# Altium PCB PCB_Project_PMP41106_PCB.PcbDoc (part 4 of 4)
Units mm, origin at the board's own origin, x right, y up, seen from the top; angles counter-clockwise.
Board outline 190 x 100 mm, 2 copper layers (Top Layer, Bottom Layer), stack 1.646 mm thick; 219 components, 122 nets, 541 pads, 61 vias.
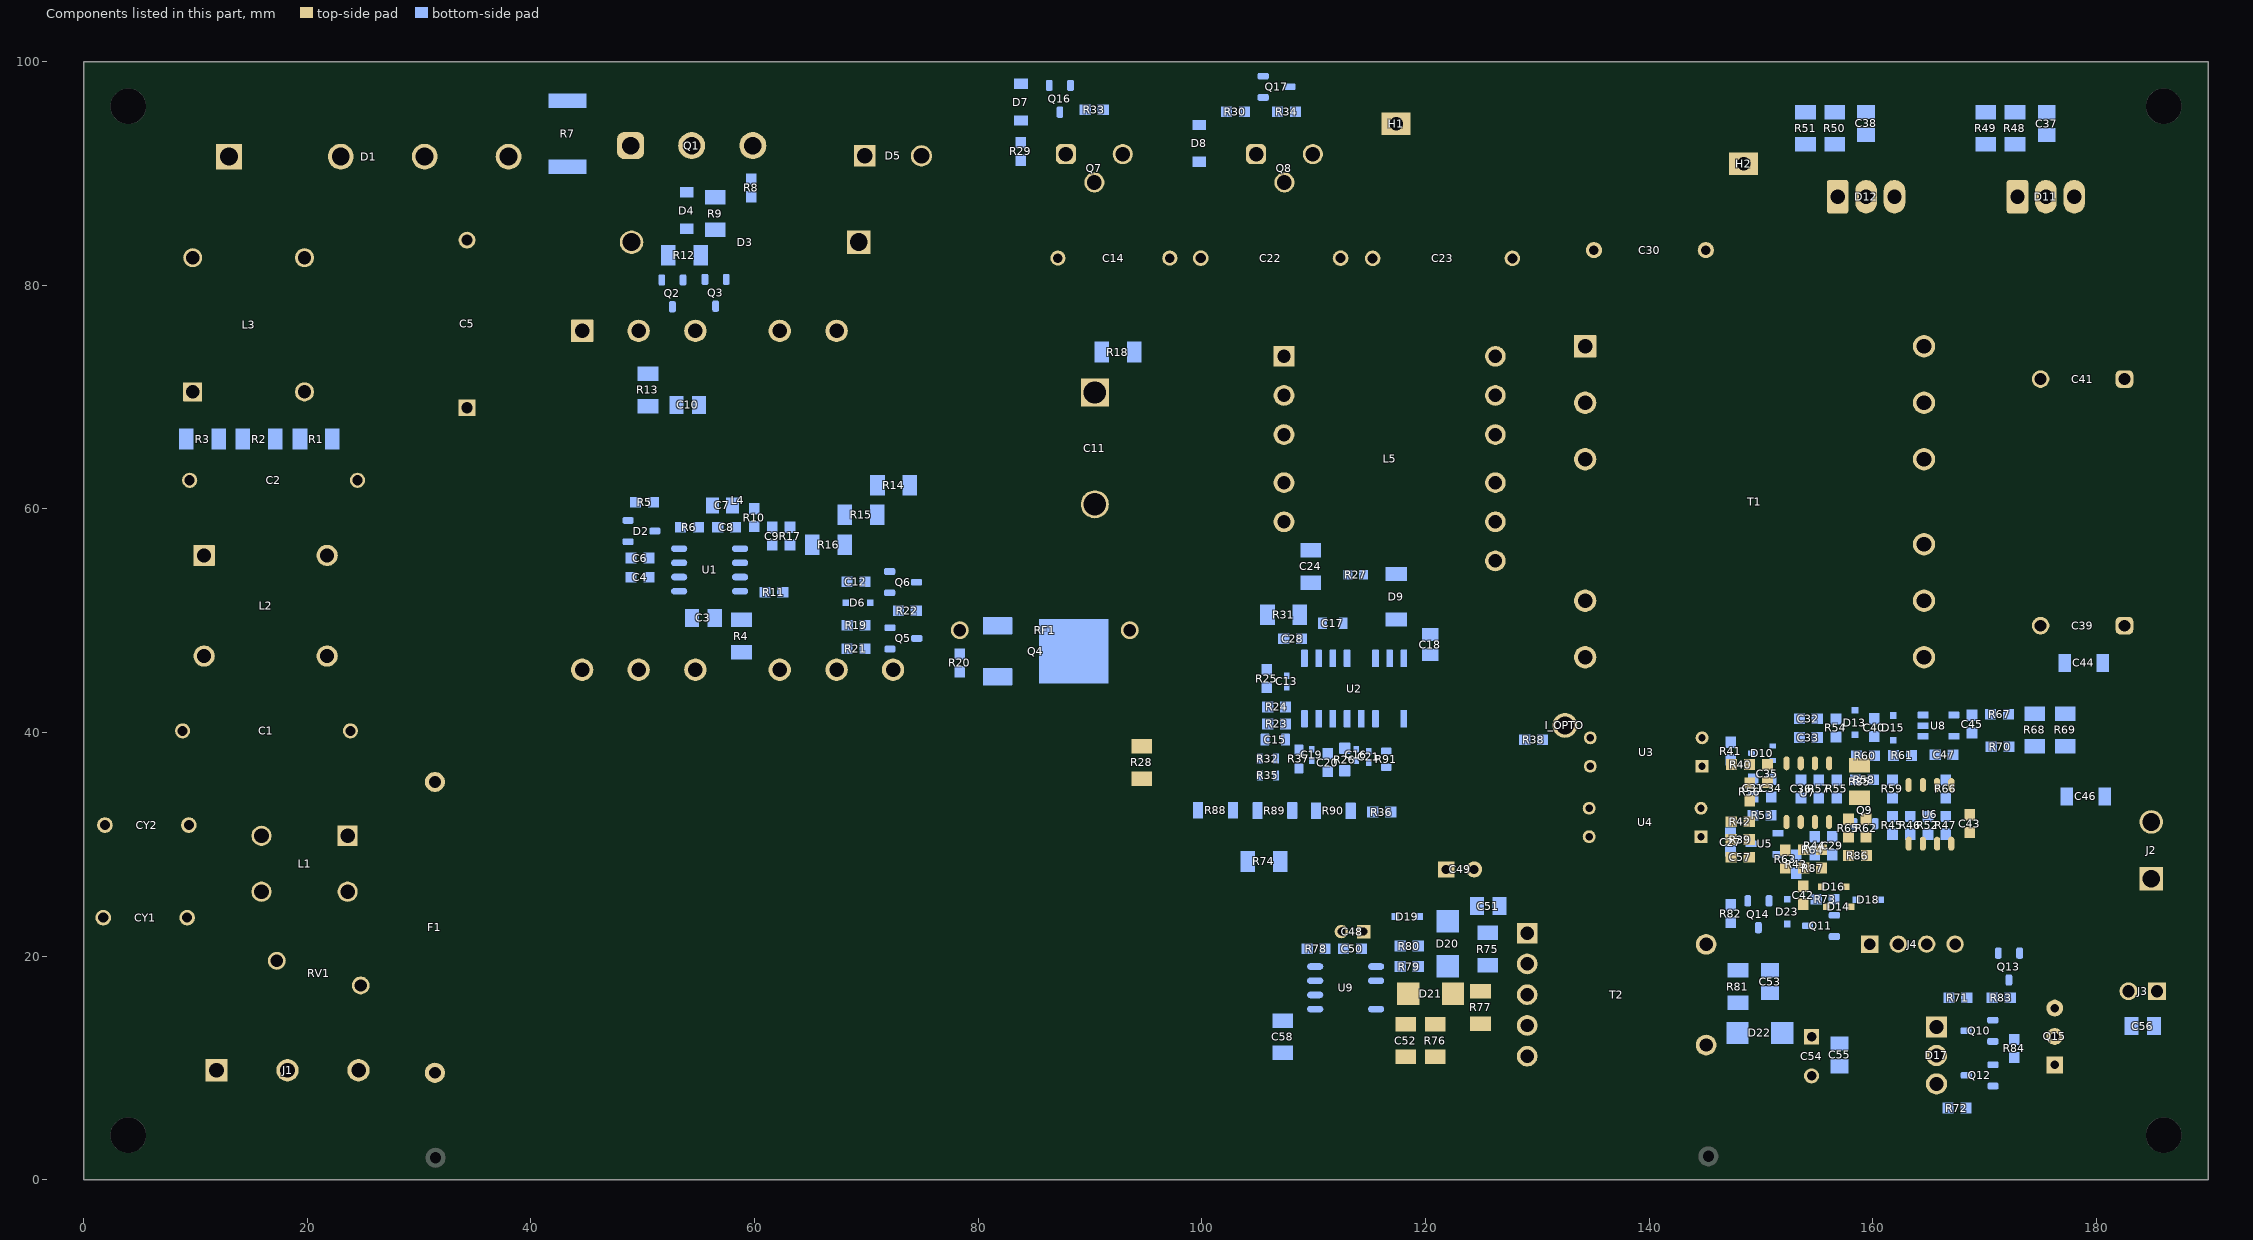
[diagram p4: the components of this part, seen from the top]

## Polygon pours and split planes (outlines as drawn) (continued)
NetD20_2 on Bottom Layer "Bottom Layer-No Net 38" (solid, pour order 150): 120.967,20.149 120.409,19.59 118.897,19.59 118.796,19.488 118.796,18.307 118.974,18.13 126.302,18.13 126.771,18.599 129.819,18.599 130.023,18.803 130.023,19.946 129.819,20.149
NetC51_1 on Bottom Layer "Bottom Layer-No Net 39" (solid, pour order 26): 124.638,22.79 125.197,22.79 125.959,23.552 125.959,25.28 126.06,25.381 127.229,25.381 127.279,25.33 127.279,23.527 126.467,22.714 126.467,21.444 126.441,21.419 124.739,21.419 124.638,21.52
PGND on Bottom Layer "Bottom Layer-No Net 40" (solid, pour order 152): 82.847,46.569 83.297,47.019 83.297,57.713 81.113,59.897 72.953,59.897 72.528,59.472 72.528,58.227 72.02,57.719 69.988,57.719 69.302,57.034 69.302,53.02 69.48,52.843 71.283,52.843 72.756,54.316 75.22,54.316 75.728,53.808 75.728,46.874 76.033,46.569
NetC49_1 on Bottom Layer "Bottom Layer-No Net 42" (solid, pour order 166): 122.631,26.067 123.266,25.432 125.146,25.432 125.247,25.33 125.247,23.603 125.044,23.4 123.215,23.4 123.012,23.197 123.012,22.13 122.911,22.028 120.98,22.028 120.853,22.155 120.853,22.867 120.523,23.197 119.126,23.197 119.024,23.298 119.024,24.137 119.863,24.975 119.863,28.727 122.631,28.727
PGND on Bottom Layer "Bottom Layer-No Net 43" (solid, pour order 170): 129.261,34.195 130.175,33.281 130.175,21.063 129.489,20.377 104.521,20.377 102.057,22.841 102.057,30.309 102.692,30.944 116.027,30.944 119.278,34.195
PGND on Bottom Layer "Bottom Layer-No Net 44" (solid, remove dead copper, pour order 174): 135.23,32.874 135.23,33.712 133.655,35.287 133.655,37.395 135.407,39.148 135.407,40.545 132.01,43.942 114.408,43.942 112.293,46.057 112.293,55.353 108.052,59.595 102.667,59.595 102.083,59.011 102.083,37.522 103.988,35.617 130.531,35.617 133.604,32.544 134.899,32.544
PGND on Bottom Layer "Bottom Layer-No Net 61" (solid, pour order 210): 57.36,73.209 54.432,70.282 54.432,61.754 64.142,61.754 64.313,61.925 64.313,72.625 63.729,73.209
NetC56_2 on Bottom Layer "Bottom Layer-No Net 45" (solid, remove dead copper, pour order 176): 176.308,17.787 175.209,16.688 175.209,15.011 175.844,14.376 175.87,14.402 180.543,14.402 182.118,12.859 183.693,12.859 183.82,12.986 183.82,17.406 183.439,17.787
NetQ13_3 on Bottom Layer "Bottom Layer-No Net 46" (solid, pour order 22): 171.958,18.364 172.517,18.364 173.279,17.602 173.279,14.275 173.939,13.614 176.784,13.614 177.19,13.208 177.19,12.217 176.835,11.862 172.212,11.862 171.704,12.37 171.704,18.11
12VS on Bottom Layer "Bottom Layer-No Net 52" (solid, pour order 214): 157.683,13.519 159.734,13.519 163.906,9.347 163.906,7.391 165.786,5.512 176.886,5.512 184.353,12.979 184.353,17.501 184.709,17.856 186.741,17.856 187.198,17.399 187.198,10.897 178.841,2.54 165.151,2.54 160.452,7.239 160.452,8.992 159.588,9.855 158.083,11.36 157.683,11.36 157.683,12.986

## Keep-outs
Keep-Out Layer:
  text ".Layer_Name" at 14.656,-23.806 h1.02

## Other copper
Top Layer:
  text ".Layer_Name" at 14.656,-23.806 h1.02
Bottom Layer:
  region net NetC22_2: 127.508,75.692 129.032,74.168 129.54,74.168 129.54,75.438 129.286,75.692
  pour cut-out: 163.754,53.905 166.268,53.905 166.903,53.27 166.903,45.904 166.065,45.066 163.627,45.066 163.017,45.676 163.017,53.194 163.703,53.88
  text ".Layer_Name" at 14.656,-23.806 h1.02

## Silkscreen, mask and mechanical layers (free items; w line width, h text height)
Top Overlay:
  circle w0.127: c186,96 r3
  circle w0.127: c186,4 r3
  circle w0.127: c4,4 r3
  circle w0.127: c4,96 r3
  text "VBAT+" at 181.635,35.871 h1.02
  text "VBAT-" at 181.635,21.952 h1.02
  text "N" at 13.919,15.545 h1.02
  text "L" at 34.925,13.259 h1.02
  text "+" at 186.614,12.808 h1.02
  text "-" at 181.356,12.732 h1.02
  text "EARTH" at 0.508,12.573 h1.02
  text "PMP41106" at 51.816,9.144 h1.52
  text ".Layer_Name" at 14.656,-23.806 h1.02
Bottom Overlay:
  lines w0.254: 110.236,35.433 109.347,34.544 98.679,34.544 97.917,35.306 ; 97.917,35.306 97.917,37.846 96.774,38.989 84.836,38.989 83.439,37.592 83.439,35.052 83.947,34.544 97.155,34.544 97.917,35.306
  text ".Layer_Name" at 14.656,-23.806 h1.02
Top Paste:
  text ".Layer_Name" at 14.656,-23.806 h1.02
Bottom Paste:
  text ".Layer_Name" at 14.656,-23.806 h1.02
Top Solder:
  text ".Layer_Name" at 14.656,-23.806 h1.02
  text ".Layer_Name" at 14.656,-23.806 h1.02
Bottom Solder:
  lines w1.524: 10.973,82.887 12.217,82.887 20.726,91.396 ; 22.276,81.795 23.851,81.795 30.404,88.348 30.404,88.957 ; 46.533,96.882 60.858,96.882 ; 159.512,79.705 178.892,79.705 183.998,74.6 ; 159.715,83.337 181.026,83.337 181.077,83.337 186.258,78.156 ; 171.552,51.994 171.552,69.545 ; 174.752,29.997 178.943,25.806 ; 174.904,52.019 174.904,69.571 ; 176.505,32.334 181.585,27.254 ; 183.185,52.502 183.185,69.494 ; 183.21,35.077 183.21,46.812 ; 186.487,35.23 186.487,69.545
  text ".Layer_Name" at 14.656,-23.806 h1.02
Drill Guide:
  text ".Layer_Name" at 14.656,-23.806 h1.02
M1 Board Outline:
  the board outline again, w0.254
  text ".Layer_Name" at 14.656,-23.806 h1.02
M2 Board Dimensions:
  rectangle: 0,-8.985 3.175,-5.81
  rectangle: 3.175,-12.16 12.7,-8.985
  lines w0.178: 0,-8.985 25.4,-8.985 ; 3.175,-12.16 3.175,-5.81 ; 6.35,-12.16 6.35,-5.81 ; 12.7,-12.16 12.7,-5.81 ; 19.05,-12.16 19.05,-5.81 ; 0,-12.16 25.4,-12.16 25.4,-5.81 0,-5.81 0,-12.16
  text ".Layer_Name" at 14.656,-23.806 h1.02
M3 3D STEP Top:
  text ".Layer_Name" at 14.656,-23.806 h1.02
M4 3D STEP Bottom:
  text ".Layer_Name" at 14.656,-23.806 h1.02
M5 Assembly Top:
  lines w0.254: -7.417,-25.626 160.223,-25.626 ; -7.417,-20.462 160.274,-20.462 ; -7.417,-15.297 -7.417,-30.791 94.31,-30.791 160.274,-30.791 160.274,-15.297 -7.404,-15.297 -7.404,-30.791 32.614,-30.791 ; 55.194,-30.791 55.194,-15.297 ; 87.376,-20.462 87.376,-15.297 ; 108.712,-20.462 108.712,-15.297 ; 124.511,-30.956 124.511,-25.804
  text "COMPONENTS MARKED 'DNP' SHOULD NOT BE POPULATED." at 29.299,-10.09 h1.02
  text "ASSEMBLY VARIANT:" at 29.286,-13.024 h1.02
  text ".VariantName" at 55.601,-13.024 h1.02
  text "PCB VIEWED FROM TOP SIDE" at -5.804,-18.654 h1.02
  text "BOARD #:" at 57.099,-18.654 h1.02
  text ".PRJ_Number" at 70.955,-18.654 h1.02
  text "REV:" at 92.405,-18.654 h1.02
  text ".PCB_Rev" at 99.809,-18.654 h1.02
  text "SVN REV:" at 113.69,-18.654 h1.02
  text ".VersionControl_RevNumber" at 126.543,-18.654 h1.02
  text "TID #:" at 57.099,-23.819 h1.02
  text ".TID" at 70.955,-23.819 h1.02
  text "PLOT NAME =" at -5.804,-29.034 h1.02
  text ".plot_File_Name" at 14.656,-29.034 h1.02
  text "GENERATED    :" at 57.15,-29.034 h1.02
  text ".Print_Date" at 79.235,-29.034 h1.02
  text ".Print_Time" at 97.752,-29.034 h1.02
  text "TEXAS INSTRUMENTS" at 129.87,-29.034 h1.02
M6 Assembly Bottom:
  lines w0.254: -7.429,-20.474 160.261,-20.474 ; -7.379,-25.639 160.261,-25.639 ; 28.334,-30.969 28.334,-25.817 ; 44.133,-20.474 44.133,-15.31 ; 65.468,-20.474 65.468,-15.31 ; 97.65,-30.804 97.65,-15.31 ; 120.231,-30.804 160.249,-30.804 160.249,-15.31 -7.429,-15.31 -7.429,-30.804 58.534,-30.804 160.261,-30.804 160.261,-15.31
  text "COMPONENTS MARKED 'DNP' SHOULD NOT BE POPULATED." at 154.991,-10.077 h1.02
  text ".VariantName" at 128.473,-13.024 h1.02
  text "ASSEMBLY VARIANT:" at 154.864,-13.024 h1.02
  text ".VersionControl_RevNumber" at 26.302,-18.667 h1.02
  text "SVN REV:" at 39.154,-18.667 h1.02
  text ".PCB_Rev" at 53.035,-18.667 h1.02
  text "REV:" at 60.439,-18.667 h1.02
  text ".PRJ_Number" at 81.89,-18.667 h1.02
  text "BOARD #:" at 95.745,-18.667 h1.02
  text "PCB VIEWED FROM BOTTOM SIDE" at 158.648,-18.667 h1.02
  text ".TID" at 81.89,-23.831 h1.02
  text "TID #:" at 95.745,-23.831 h1.02
  text "TEXAS INSTRUMENTS" at 22.974,-29.047 h1.02
  text ".Print_Time" at 55.093,-29.047 h1.02
  text ".Print_Date" at 73.609,-29.047 h1.02
  text "GENERATED    :" at 95.694,-29.047 h1.02
  text ".plot_File_Name" at 138.189,-29.047 h1.02
  text "PLOT NAME =" at 158.648,-29.047 h1.02
M9 Title Sheet:
  drawing of 57 lines, arcs and shapes, not listed
  text "1" at 18.792,202.127 h1.02
  text "2" at 82.182,202.127 h1.02
  text "3" at 145.411,202.127 h1.02
  text "4" at 209.08,202.127 h1.02
  text "5" at 272.555,202.127 h1.02
  text "6" at 336.182,202.127 h1.02
  text "A" at -10.579,173.095 h1.02
  text "A" at 365.341,173.095 h1.02
  text "B" at -10.579,112.643 h1.02
  text "B" at 365.341,112.643 h1.02
  text "C" at -10.579,52.318 h1.02
  text "C" at 365.341,52.318 h1.02
  text "PROJECT TITLE:" at 288.125,5.048 h1.02
  text ".PRJ_Title" at 289.395,1.662 h1.02
  text "DESIGNED FOR:" at 288.125,-2.597 h1.02
  text ".PRJ_Customer" at 289.395,-6.153 h1.02
  text "D" at -10.579,-7.88 h1.02
  text "D" at 365.341,-7.88 h1.02
  text "FILE NAME:" at 288.125,-10.217 h1.02
  text ".PCB_File_Name_No_Path" at 289.395,-13.265 h1.02
  text "Texas Instruments (TI) and/or its licensors do not warrant the accuracy or completeness of this specification" at 161.9,-17.376 h1.02
  text "ENGINEER:" at 288.125,-17.583 h1.02
  text "LAYOUT BY:" at 326.352,-17.583 h1.02
  text "or any information contained therein. TI and/or its licensors do not warrant that this design will meet" at 160.757,-20.237 h1.02
  text ".PRJ_Engineer" at 289.395,-21.52 h1.02
  text ".PCB_Layout" at 327.635,-21.52 h1.02
  text "the specifications, will be suitable for your application or fit for any particular purpose, or will operate in" at 160.757,-23.099 h1.02
  text ".Layer_Name" at 14.656,-23.806 h1.02
  text "ALTIUM DESIGNER VERSION:" at 326.352,-25.457 h1.02
  text "an implementation. TI and/or its licensors do not warrant that the design is production worthy. You should" at 160.757,-25.961 h1.02
  text "completely validate and test your design implementation to confirm the system functionality for your application." at 161.9,-28.822 h1.02
  text ".print_Scale" at 289.395,-28.843 h1.02
  text ".Application_BuildNumber" at 327.635,-28.843 h1.02
  text "1" at 18.792,-34.093 h1.02
  text "2" at 82.182,-34.093 h1.02
  text "3" at 145.411,-34.093 h1.02
  text "4" at 209.08,-34.093 h1.02
  text "5" at 272.555,-34.093 h1.02
  text "6" at 336.182,-34.093 h1.02
M10 Fab Notes:
  drawing of 189 lines, arcs and shapes, not listed
  text "DESIGN INFORMATION" at 314.503,159.447 h1.02
  text "MIN. TRACK WIDTH:" at 298.131,156.091 h1.02
  text "8" at 325.976,156.091 h1.02
  text "MIL" at 329.907,156.091 h1.02
  text "MIN. CLEARANCE:" at 298.131,152.938 h1.02
  text "0.2" at 324.452,152.938 h1.02
  text "mm" at 329.907,152.938 h1.02
  text "MIN. VIA PAD SIZE:" at 298.131,149.785 h1.02
  text "24" at 325.214,149.785 h1.02
  text "MIL" at 329.907,149.785 h1.02
  text "0.05mm (2MIL)" at 315.784,146.486 h1.02
  text "MINIMUM ANNULAR RING" at 289.769,146.277 h1.02
  text "EXTERNAL" at 333.768,146.277 h1.02
  text "PER" at 294.849,143.48 h1.02
  text "IPC-D-275 CLASS 2 LEVEL C" at 300.437,143.48 h1.02
  text "MIL, HOLES" at 338.238,140.928 h1.02
  text "+/-" at 328.27,140.709 h1.02
  text "+/-" at 349.961,140.709 h1.02
  text "REGISTRATION TOLERANCES:" at 289.769,140.682 h1.02
  text "METAL" at 320.243,140.682 h1.02
  text "5" at 334.879,140.683 h1.02
  text "3" at 356.037,140.683 h1.02
  text "MIL" at 358.99,140.682 h1.02
  text "HOLE SIZE TOLERANCE (UNLESS OTHERWISE SPECIFIED):" at 289.769,138.185 h1.02
  text "+/-" at 349.961,138.112 h1.02
  text "3" at 356.037,138.085 h1.02
  text "MIL" at 358.99,138.085 h1.02
  text "MATERIAL:" at 287.87,134.589 h1.02
  text "FR-4 High Tg" at 312.926,131.324 h1.02
  text "X" at 309.257,131.122 h1.02
  text "FR-408" at 298.563,131.007 h1.02
  text "OTHER" at 336.358,131.007 h1.02
  text "62 MIL (1.6mm) +/-10%" at 306.694,127.374 h1.02
  text "X" at 303.643,127.312 h1.02
  text "THICKNESS:" at 289.769,127.165 h1.02
  text "OTHER" at 339.33,127.165 h1.02
  text "TOLERANCE:" at 289.769,123.652 h1.02
  text "X" at 311.314,123.652 h1.02
  text "ANSI IPC-6012 TYPE 3 CLASS 2" at 315.836,123.652 h1.02
  text "OTHER +/-" at 315.835,119.989 h1.02
  text "BOW & TWIST:" at 289.769,116.302 h1.02
  text "X" at 311.314,116.302 h1.02
  text "ANSI IPC-6012 TYPE 3 CLASS 2" at 315.836,116.302 h1.02
  text "OTHER +/-" at 315.835,112.576 h1.02
  text "DRILLING:" at 287.87,109.258 h1.02
  text "NC_DRILL FILES" at 332.599,106.586 h1.02
  text "REFERENCE:" at 289.769,106.486 h1.02
  text "X" at 306.463,106.484 h1.02
  text "AS SHOWN" at 310.984,106.486 h1.02
  text "X" at 329.348,106.486 h1.02
  text "OTHER" at 340.168,102.873 h1.02
  text "PTH COPPER THICKNESS:" at 289.761,102.783 h1.02
  text "X" at 318.697,102.783 h1.02
  text "20-30 um" at 321.948,102.783 h1.02
  text "BOARD FINISH:" at 287.87,99.034 h1.02
  text "SILKSCREEN:" at 291.812,96.237 h1.02
  text "X" at 316.14,96.237 h1.02
  text "TOP" at 319.112,96.237 h1.02
  text "X" at 329.094,96.237 h1.02
  text "BOTTOM" at 332.091,96.237 h1.02
  text "SILKSCREEN COLOR:" at 291.812,92.295 h1.02
  text "X" at 316.115,92.295 h1.02
  text "WHITE" at 319.112,92.295 h1.02
  text "OTHER" at 332.091,92.295 h1.02
  text "X" at 319.442,88.652 h1.02
  text "GREEN" at 322.439,88.652 h1.02
  text "OTHER" at 338.136,88.652 h1.02
  text "SOLDER RESIST COLOR:" at 291.812,88.477 h1.02
  text "X" at 319.442,84.734 h1.02
  text "MATTE" at 322.439,84.734 h1.02
  text "SEMI-GLOSS" at 338.125,84.717 h1.02
  text "IMMERSION GOLD (ENIG)" at 314.819,80.345 h1.02
  text "ENEPIG" at 348.793,80.162 h1.02
  text "SURFACE FINISH:" at 287.87,80.136 h1.02
  text "X" at 310.298,80.136 h1.02
  text "IMM. TIN/SILVER OR EQUIV" at 296.24,76.649 h1.02
  text "OTHER" at 332.599,76.549 h1.02
  text "ARRAY/PANEL:" at 287.87,72.602 h1.02
  text "CUT AND TRIM PER M1 BOARD OUTLINE" at 314.819,72.393 h1.02
  text "N.C. ROUTE" at 314.819,68.94 h1.02
  text "X" at 332.295,68.94 h1.02
  text "V. SCORE" at 336.816,68.94 h1.02
  text "CERTIFICATION:" at 287.87,65.66 h1.02
  text "MATERIALS AND WORKMANSHIP FOR ALL PCBS" at 306.285,65.66 h1.02
  text "TO MEET OR EXCEED THE REQUIREMENTS OF:" at 306.285,63.271 h1.02
  text "X" at 297.078,60.003 h1.02
  text "ANSI IPC-A-600F CLASS ->" at 300.329,60.003 h1.02
  text "X" at 342.188,60.003 h1.02
  text "2" at 344.982,60.003 h1.02
  text "1" at 336.981,59.965 h1.02
  text "3" at 353.973,59.965 h1.02
  text "X" at 317.702,56.252 h1.02
  text "RoHS" at 320.953,56.252 h1.02
  text "OTHER" at 337.321,56.252 h1.02
  text "PER ORDER" at 347.407,56.252 h1.02
  text "ALL BOARDS MUST MEET OR EXCEED UL94-V0 REQUIREMENTS." at 288.569,52.345 h1.02
  text "PCB MUST BEAR THE UL94V-0 UL REGISTERED MATERIAL ID NUMBER" at 288.569,49.397 h1.02
  text "ADDITIONAL REQUIREMENTS:" at 287.87,45.094 h1.02
  text "MICROSECTION:" at 289.769,42.373 h1.02
  text "YES" at 312.775,42.373 h1.02
  text "REQUIRED" at 334.657,38.707 h1.02
  text "BARE BOARD ELEC. TEST:" at 289.769,38.634 h1.02
  text "NONE" at 322.935,38.634 h1.02
  text "X" at 331.66,38.634 h1.02
  text "PER ORDER" at 349.693,38.634 h1.02
  text "XX MIL VIAS REQUIRE NON-CONDUCTIVE FILL AND PLANARIZE" at 294.04,33.428 h1.02
  text "XX MIL VIAS REQUIRE CONDUCTIVE FILL AND PLANARIZE" at 294.243,30.787 h1.02
  text "OUTER XX MIL TRACES REQUIRE 50 OHM SINGLE-ENDED IMPEDANCE" at 294.218,26.637 h1.02
  text "LAYER 2 & 3 (INNER LAYERS) XX MIL WIDE, XX MIL SPACE / TRACES REQUIRE 100 OHM DIFFERENTIAL IMPEDANCE" at 294.015,20.65 h1.02
  text ".Layer_Name" at 14.656,-23.806 h1.02
M11 Gerber Information:
  lines w0.254: -7.417,-25.626 160.223,-25.626 ; -7.417,-20.462 160.274,-20.462 ; -7.417,-15.297 -7.417,-30.791 94.31,-30.791 160.274,-30.791 160.274,-15.297 -7.404,-15.297 -7.404,-30.791 32.614,-30.791 ; 55.194,-30.791 55.194,-15.297 ; 87.376,-20.462 87.376,-15.297 ; 108.712,-20.462 108.712,-15.297 ; 124.511,-30.956 124.511,-25.804
  text "ALL ARTWORK VIEWED FROM TOP SIDE" at -5.804,-18.654 h1.02
  text "BOARD #:" at 57.099,-18.654 h1.02
  text ".PRJ_Number" at 70.955,-18.654 h1.02
  text "REV:" at 92.405,-18.654 h1.02
  text ".PCB_Rev" at 99.809,-18.654 h1.02
  text "SVN REV:" at 113.69,-18.654 h1.02
  text ".VersionControl_RevNumber" at 126.543,-18.654 h1.02
  text "LAYER NAME =" at -5.804,-23.806 h1.02
  text "TID #:" at 57.099,-23.819 h1.02
  text ".TID" at 70.955,-23.819 h1.02
  text "PLOT NAME =" at -5.804,-29.034 h1.02
  text ".plot_File_Name" at 14.656,-29.034 h1.02
  text "GENERATED    :" at 57.15,-29.034 h1.02
  text ".Print_Date" at 79.235,-29.034 h1.02
  text ".Print_Time" at 97.752,-29.034 h1.02
  text "TEXAS INSTRUMENTS" at 129.87,-29.034 h1.02
M12 Stackup:
  drawing of 191 lines, arcs and shapes, not listed
  text "Layer" at 248.611,198.215 h1.02
  text "Name" at 255.722,198.215 h1.02
  text "Material" at 271.635,198.215 h1.02
  text "Thickness" at 286.363,198.215 h1.02
  text "Constant" at 297.536,198.215 h1.02
  text "Board Layer Stack" at 307.355,198.215 h1.02
  text "Top Overlay" at 255.722,196.183 h1.02
  text "Top Solder" at 255.722,194.151 h1.02
  text "Solder Resist" at 271.635,194.151 h1.02
  text "0.40mil" at 286.363,194.151 h1.02
  text "3.5" at 297.536,194.151 h1.02
  text "1" at 248.611,192.119 h1.02
  text "Top Layer" at 255.722,192.119 h1.02
  text "2.80mil" at 286.363,192.119 h1.02
  text "Dielectric1" at 255.722,190.087 h1.02
  text "FR-4" at 271.635,190.087 h1.02
  text "59.20mil" at 286.363,190.087 h1.02
  text "4.8" at 297.536,190.087 h1.02
  text "2" at 248.611,188.055 h1.02
  text "Bottom Layer" at 255.722,188.055 h1.02
  text "2.80mil" at 286.363,188.055 h1.02
  text "Bottom Solder" at 255.722,186.023 h1.02
  text "Solder Resist" at 271.635,186.023 h1.02
  text "0.40mil" at 286.363,186.023 h1.02
  text "3.5" at 297.536,186.023 h1.02
  text "Bottom Overlay" at 255.722,183.991 h1.02
  text ".Layer_Name" at 14.656,-23.806 h1.02
M13 Component Bodies Top:
  text ".Layer_Name" at 14.656,-23.806 h1.02
M14 Component Bodies Bottom:
  text ".Layer_Name" at 14.656,-23.806 h1.02
M15 Courtyards Top:
  text ".Layer_Name" at 14.656,-23.806 h1.02
M16 Courtyards Bottom:
  text ".Layer_Name" at 14.656,-23.806 h1.02
Drill Drawing:
  drawing of 320 lines, arcs and shapes, not listed
  text "Symbol" at 501.868,565.855 h1.22
  text "Quantity" at 506.957,565.855 h1.22
  text "Finished Hole Size" at 512.579,565.855 h1.22
  text "Plated" at 523.358,565.855 h1.22
  text "Hole Type" at 527.746,565.855 h1.22
  text "Drill Layer Pair" at 534.099,565.855 h1.22
  text "Hole Tolerance" at 546.364,565.855 h1.22
  text "4" at 506.957,563.75 h1.02
  text "125.98mil (3.200mm)" at 512.579,563.75 h1.02
  text "NPTH" at 523.358,563.75 h1.02
  text "Round" at 527.746,563.75 h1.02
  text "Top Layer - Bottom Layer" at 534.099,563.75 h1.02
  text "L" at 501.381,563.496 h0.94
  text "9" at 506.957,561.645 h1.02
  text "8.00mil (0.203mm)" at 512.579,561.645 h1.02
  text "PTH" at 523.358,561.645 h1.02
  text "Round" at 527.746,561.645 h1.02
  text "Top Layer - Bottom Layer" at 534.099,561.645 h1.02
  text "K" at 501.381,561.391 h0.94
  text "52" at 506.957,559.539 h1.02
  text "12.00mil (0.305mm)" at 512.579,559.539 h1.02
  text "PTH" at 523.358,559.539 h1.02
  text "Round" at 527.746,559.539 h1.02
  text "Top Layer - Bottom Layer" at 534.099,559.539 h1.02
  text "E" at 501.381,559.286 h0.94
  text "8" at 506.957,557.434 h1.02
  text "25.59mil (0.650mm)" at 512.579,557.434 h1.02
  text "PTH" at 523.358,557.434 h1.02
  text "Round" at 527.746,557.434 h1.02
  text "Top Layer - Bottom Layer" at 534.099,557.434 h1.02
  text "1" at 506.957,555.329 h1.02
  text "28.00mil (0.711mm)" at 512.579,555.329 h1.02
  text "PTH" at 523.358,555.329 h1.02
  text "Round" at 527.746,555.329 h1.02
  text "Top Layer - Bottom Layer" at 534.099,555.329 h1.02
  text "1" at 506.957,553.224 h1.02
  text "28.01mil (0.712mm)" at 512.579,553.224 h1.02
  text "PTH" at 523.358,553.224 h1.02
  text "Round" at 527.746,553.224 h1.02
  text "Top Layer - Bottom Layer" at 534.099,553.224 h1.02
  text "3" at 506.957,551.119 h1.02
  text "29.53mil (0.750mm)" at 512.579,551.119 h1.02
  text "PTH" at 523.358,551.119 h1.02
  text "Round" at 527.746,551.119 h1.02
  text "Top Layer - Bottom Layer" at 534.099,551.119 h1.02
  text "2" at 506.957,549.014 h1.02
  text "31.00mil (0.787mm)" at 512.579,549.014 h1.02
  text "PTH" at 523.358,549.014 h1.02
  text "Round" at 527.746,549.014 h1.02
  text "Top Layer - Bottom Layer" at 534.099,549.014 h1.02
  text "6" at 506.957,546.908 h1.02
  text "33.47mil (0.850mm)" at 512.579,546.908 h1.02
  text "PTH" at 523.358,546.908 h1.02
  text "Round" at 527.746,546.908 h1.02
  text "Top Layer - Bottom Layer" at 534.099,546.908 h1.02
  text "12" at 506.957,544.803 h1.02
  text "35.43mil (0.900mm)" at 512.579,544.803 h1.02
  text "PTH" at 523.358,544.803 h1.02
  text "Round" at 527.746,544.803 h1.02
  text "Top Layer - Bottom Layer" at 534.099,544.803 h1.02
  text "4" at 506.957,542.698 h1.02
  text "39.37mil (1.000mm)" at 512.579,542.698 h1.02
  text "PTH" at 523.358,542.698 h1.02
  text "Round" at 527.746,542.698 h1.02
  text "Top Layer - Bottom Layer" at 534.099,542.698 h1.02
  text "D" at 501.381,542.444 h0.94
  text "4" at 506.957,540.593 h1.02
  text "40.16mil (1.020mm)" at 512.579,540.593 h1.02
  text "PTH" at 523.358,540.593 h1.02
  text "Round" at 527.746,540.593 h1.02
  text "Top Layer - Bottom Layer" at 534.099,540.593 h1.02
  text "I" at 501.537,540.339 h0.94
  text "2" at 506.957,538.488 h1.02
  text "41.00mil (1.041mm)" at 512.579,538.488 h1.02
  text "PTH" at 523.358,538.488 h1.02
  text "Round" at 527.746,538.488 h1.02
  text "Top Layer - Bottom Layer" at 534.099,538.488 h1.02
  text "C" at 501.381,538.234 h0.94
  text "4" at 506.957,536.383 h1.02
  text "41.34mil (1.050mm)" at 512.579,536.383 h1.02
  text "PTH" at 523.358,536.383 h1.02
  text "Round" at 527.746,536.383 h1.02
  text "Top Layer - Bottom Layer" at 534.099,536.383 h1.02
  text "G" at 501.381,536.129 h0.94
  text "2" at 506.957,534.278 h1.02
  text "42.91mil (1.090mm)" at 512.579,534.278 h1.02
  text "PTH" at 523.358,534.278 h1.02
  text "Round" at 527.746,534.278 h1.02
  text "Top Layer - Bottom Layer" at 534.099,534.278 h1.02
  text "4" at 506.957,532.172 h1.02
  text "43.31mil (1.100mm)" at 512.579,532.172 h1.02
  text "PTH" at 523.358,532.172 h1.02
  text "Round" at 527.746,532.172 h1.02
  text "Top Layer - Bottom Layer" at 534.099,532.172 h1.02
  text "22" at 506.957,530.067 h1.02
  text "47.24mil (1.200mm)" at 512.579,530.067 h1.02
  text "PTH" at 523.358,530.067 h1.02
  text "Round" at 527.746,530.067 h1.02
  text "Top Layer - Bottom Layer" at 534.099,530.067 h1.02
  text "7" at 506.957,527.962 h1.02
  text "49.21mil (1.250mm)" at 512.579,527.962 h1.02
  text "PTH" at 523.358,527.962 h1.02
  text "Round" at 527.746,527.962 h1.02
  text "Top Layer - Bottom Layer" at 534.099,527.962 h1.02
  text "A" at 501.381,527.708 h0.94
  text "6" at 506.957,525.857 h1.02
  text "50.00mil (1.270mm)" at 512.579,525.857 h1.02
  text "PTH" at 523.358,525.857 h1.02
  text "Round" at 527.746,525.857 h1.02
  text "Top Layer - Bottom Layer" at 534.099,525.857 h1.02
  text "F" at 501.381,525.603 h0.94
  text "35" at 506.957,523.752 h1.02
  text "51.18mil (1.300mm)" at 512.579,523.752 h1.02
  text "PTH" at 523.358,523.752 h1.02
  text "Round" at 527.746,523.752 h1.02
  text "Top Layer - Bottom Layer" at 534.099,523.752 h1.02
  text "B" at 501.381,523.498 h0.94
  text "2" at 506.957,521.647 h1.02
  text "55.12mil (1.400mm)" at 512.579,521.647 h1.02
  text "PTH" at 523.358,521.647 h1.02
  text "Round" at 527.746,521.647 h1.02
  text "Top Layer - Bottom Layer" at 534.099,521.647 h1.02
  text "3" at 506.957,519.541 h1.02
  text "62.00mil (1.575mm)" at 512.579,519.541 h1.02
  text "PTH" at 523.358,519.541 h1.02
  text "Round" at 527.746,519.541 h1.02
  text "Top Layer - Bottom Layer" at 534.099,519.541 h1.02
  text "H" at 501.381,519.288 h0.94
  text "8" at 506.957,517.436 h1.02
  text "62.99mil (1.600mm)" at 512.579,517.436 h1.02
  text "PTH" at 523.358,517.436 h1.02
  text "Round" at 527.746,517.436 h1.02
  text "Top Layer - Bottom Layer" at 534.099,517.436 h1.02
  text "1" at 506.957,515.331 h1.02
  text "63.00mil (1.600mm)" at 512.579,515.331 h1.02
  text "PTH" at 523.358,515.331 h1.02
  text "Round" at 527.746,515.331 h1.02
  text "Top Layer - Bottom Layer" at 534.099,515.331 h1.02
  text "J" at 501.381,515.077 h0.94
  text "2" at 506.957,513.226 h1.02
  text "78.74mil (2.000mm)" at 512.579,513.226 h1.02
  text "PTH" at 523.358,513.226 h1.02
  text "Round" at 527.746,513.226 h1.02
  text "Top Layer - Bottom Layer" at 534.099,513.226 h1.02
  text "2" at 506.957,511.121 h1.02
  text "47.24mil (1.200mm)" at 512.579,511.121 h1.02
  text "PTH" at 523.358,511.121 h1.02
  text "Rectangle" at 527.746,511.121 h1.02
  text "Top Layer - Bottom Layer" at 534.099,511.121 h1.02
  text "206 Total" at 506.957,509.016 h1.02
  text "Slot definitions :" at 501.868,507.542 h1.02
  text "Routed Path Length" at 509.5,507.542 h1.02
  text "= Calculated from tool start centre position to tool end centre position." at 518.639,507.542 h1.02
  text "Hole Length" at 509.5,506.7 h1.02
  text "= Routed Path Length + Tool Size = Slot length as defined in the PCB layout" at 515.256,506.7 h1.02
  text "Symbol" at 200.548,97.91 h1.83
  text "Count" at 208.182,97.91 h1.83
  text "Hole Size" at 215.861,97.91 h1.83
  text "Plated" at 230.845,97.91 h1.83
  text "Hole Type" at 237.427,97.91 h1.83
  text "Drill Layer Pair" at 246.956,97.91 h1.83
  text "Hole Tolerance" at 265.354,97.91 h1.83
  text "9" at 208.182,94.752 h1.52
  text "8.00mil (0.203mm)" at 215.861,94.752 h1.52
  text "PTH" at 230.845,94.752 h1.52
  text "Round" at 237.427,94.752 h1.52
  text "Top Layer - Bottom Layer" at 246.956,94.752 h1.52
  text "K" at 199.906,94.498 h1.4
  text "52" at 208.182,91.594 h1.52
  text "12.00mil (0.305mm)" at 215.861,91.594 h1.52
  text "PTH" at 230.845,91.594 h1.52
  text "Round" at 237.427,91.594 h1.52
  text "Top Layer - Bottom Layer" at 246.956,91.594 h1.52
  text "E" at 199.906,91.341 h1.4
  text "8" at 208.182,88.437 h1.52
  text "25.59mil (0.650mm)" at 215.861,88.437 h1.52
  text "PTH" at 230.845,88.437 h1.52
  text "Round" at 237.427,88.437 h1.52
  text "Top Layer - Bottom Layer" at 246.956,88.437 h1.52
  text "1" at 208.182,85.279 h1.52
  text "28.00mil (0.711mm)" at 215.861,85.279 h1.52
  text "PTH" at 230.845,85.279 h1.52
  text "Round" at 237.427,85.279 h1.52
  text "Top Layer - Bottom Layer" at 246.956,85.279 h1.52
  text "1" at 208.182,82.121 h1.52
  text "28.01mil (0.712mm)" at 215.861,82.121 h1.52
  text "PTH" at 230.845,82.121 h1.52
  text "Round" at 237.427,82.121 h1.52
  text "Top Layer - Bottom Layer" at 246.956,82.121 h1.52
  text "3" at 208.182,78.963 h1.52
  text "29.53mil (0.750mm)" at 215.861,78.963 h1.52
  text "PTH" at 230.845,78.963 h1.52
  text "Round" at 237.427,78.963 h1.52
  text "Top Layer - Bottom Layer" at 246.956,78.963 h1.52
  text "2" at 208.182,75.806 h1.52
  text "31.00mil (0.787mm)" at 215.861,75.806 h1.52
  text "PTH" at 230.845,75.806 h1.52
  text "Round" at 237.427,75.806 h1.52
  text "Top Layer - Bottom Layer" at 246.956,75.806 h1.52
  text "6" at 208.182,72.648 h1.52
  text "33.47mil (0.850mm)" at 215.861,72.648 h1.52
  text "PTH" at 230.845,72.648 h1.52
  text "Round" at 237.427,72.648 h1.52
  text "Top Layer - Bottom Layer" at 246.956,72.648 h1.52
  text "12" at 208.182,69.49 h1.52
  text "35.43mil (0.900mm)" at 215.861,69.49 h1.52
  text "PTH" at 230.845,69.49 h1.52
  text "Round" at 237.427,69.49 h1.52
  text "Top Layer - Bottom Layer" at 246.956,69.49 h1.52
  text "4" at 208.182,66.332 h1.52
  text "39.37mil (1.000mm)" at 215.861,66.332 h1.52
  text "PTH" at 230.845,66.332 h1.52
  text "Round" at 237.427,66.332 h1.52
  text "Top Layer - Bottom Layer" at 246.956,66.332 h1.52
  text "D" at 199.906,66.079 h1.4
  text "4" at 208.182,63.175 h1.52
  text "40.16mil (1.020mm)" at 215.861,63.175 h1.52
  text "PTH" at 230.845,63.175 h1.52
  text "Round" at 237.427,63.175 h1.52
  text "Top Layer - Bottom Layer" at 246.956,63.175 h1.52
  text "I" at 200.14,62.921 h1.4
  text "2" at 208.182,60.017 h1.52
  text "41.00mil (1.041mm)" at 215.861,60.017 h1.52
  text "PTH" at 230.845,60.017 h1.52
  text "Round" at 237.427,60.017 h1.52
  text "Top Layer - Bottom Layer" at 246.956,60.017 h1.52
  text "C" at 199.906,59.763 h1.4
  text "4" at 208.182,56.859 h1.52
  text "41.34mil (1.050mm)" at 215.861,56.859 h1.52
  text "PTH" at 230.845,56.859 h1.52
  text "Round" at 237.427,56.859 h1.52
  text "Top Layer - Bottom Layer" at 246.956,56.859 h1.52
  text "G" at 199.906,56.606 h1.4
  text "2" at 208.182,53.702 h1.52
  text "42.91mil (1.090mm)" at 215.861,53.702 h1.52
  text "PTH" at 230.845,53.702 h1.52
  text "Round" at 237.427,53.702 h1.52
  text "Top Layer - Bottom Layer" at 246.956,53.702 h1.52
  text "4" at 208.182,50.544 h1.52
  text "43.31mil (1.100mm)" at 215.861,50.544 h1.52
  text "PTH" at 230.845,50.544 h1.52
  text "Round" at 237.427,50.544 h1.52
  text "Top Layer - Bottom Layer" at 246.956,50.544 h1.52
  text "22" at 208.182,47.386 h1.52
  text "47.24mil (1.200mm)" at 215.861,47.386 h1.52
  text "PTH" at 230.845,47.386 h1.52
  text "Round" at 237.427,47.386 h1.52
  text "Top Layer - Bottom Layer" at 246.956,47.386 h1.52
  text "2" at 208.182,44.228 h1.52
  text "47.24mil (1.200mm)" at 215.861,44.228 h1.52
  text "PTH" at 230.845,44.228 h1.52
  text "Rectangle" at 237.427,44.228 h1.52
  text "Top Layer - Bottom Layer" at 246.956,44.228 h1.52
  text "7" at 208.182,41.071 h1.52
  text "49.21mil (1.250mm)" at 215.861,41.071 h1.52
  text "PTH" at 230.845,41.071 h1.52
  text "Round" at 237.427,41.071 h1.52
  text "Top Layer - Bottom Layer" at 246.956,41.071 h1.52
  text "A" at 199.906,40.817 h1.4
  text "6" at 208.182,37.913 h1.52
  text "50.00mil (1.270mm)" at 215.861,37.913 h1.52
  text "PTH" at 230.845,37.913 h1.52
  text "Round" at 237.427,37.913 h1.52
  text "Top Layer - Bottom Layer" at 246.956,37.913 h1.52
  text "F" at 199.906,37.659 h1.4
  text "35" at 208.182,34.755 h1.52
  text "51.18mil (1.300mm)" at 215.861,34.755 h1.52
  text "PTH" at 230.845,34.755 h1.52
  text "Round" at 237.427,34.755 h1.52
  text "Top Layer - Bottom Layer" at 246.956,34.755 h1.52
  text "B" at 199.906,34.501 h1.4
  text "2" at 208.182,31.597 h1.52
  text "55.12mil (1.400mm)" at 215.861,31.597 h1.52
  text "PTH" at 230.845,31.597 h1.52
  text "Round" at 237.427,31.597 h1.52
  text "Top Layer - Bottom Layer" at 246.956,31.597 h1.52
  text "3" at 208.182,28.44 h1.52
  text "62.00mil (1.575mm)" at 215.861,28.44 h1.52
  text "PTH" at 230.845,28.44 h1.52
  text "Round" at 237.427,28.44 h1.52
  text "Top Layer - Bottom Layer" at 246.956,28.44 h1.52
  text "H" at 199.906,28.186 h1.4
  text "8" at 208.182,25.282 h1.52
  text "62.99mil (1.600mm)" at 215.861,25.282 h1.52
  text "PTH" at 230.845,25.282 h1.52
  text "Round" at 237.427,25.282 h1.52
  text "Top Layer - Bottom Layer" at 246.956,25.282 h1.52
  text "1" at 208.182,22.124 h1.52
  text "63.00mil (1.600mm)" at 215.861,22.124 h1.52
  text "PTH" at 230.845,22.124 h1.52
  text "Round" at 237.427,22.124 h1.52
  text "Top Layer - Bottom Layer" at 246.956,22.124 h1.52
  text "J" at 199.906,21.87 h1.4
  text "2" at 208.182,18.967 h1.52
  text "78.74mil (2.000mm)" at 215.861,18.967 h1.52
  text "PTH" at 230.845,18.967 h1.52
  text "Round" at 237.427,18.967 h1.52
  text "Top Layer - Bottom Layer" at 246.956,18.967 h1.52
  text "4" at 208.182,15.809 h1.52
  text "125.98mil (3.200mm)" at 215.861,15.809 h1.52
  text "NPTH" at 230.845,15.809 h1.52
  text "Round" at 237.427,15.809 h1.52
  text "Top Layer - Bottom Layer" at 246.956,15.809 h1.52
  text "L" at 199.906,15.555 h1.4
  text "206 Total" at 208.182,12.651 h1.52
  text "Slot definitions :" at 200.548,10.441 h1.52
  text "Routed Path Length" at 211.996,10.441 h1.52
  text "= Calculated from tool start centre position to tool end centre position." at 225.706,10.441 h1.52
  text "Hole Length" at 211.996,9.178 h1.52
  text "= Routed Path Length + Tool Size = Slot length as defined in the PCB layout" at 220.631,9.178 h1.52
  text ".Layer_Name" at 14.656,-23.806 h1.02
Mechanical 17:
  text ".Layer_Name" at 14.656,-23.806 h1.02
Mechanical 18:
  text ".Layer_Name" at 14.656,-23.806 h1.02
Mechanical 19:
  text ".Layer_Name" at 14.656,-23.806 h1.02

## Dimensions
0,-12.16 to 25.4,-12.16 on M2 Board Dimensions
0,0 to 0,100 on M2 Board Dimensions
0,0 to 190,0 on M2 Board Dimensions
